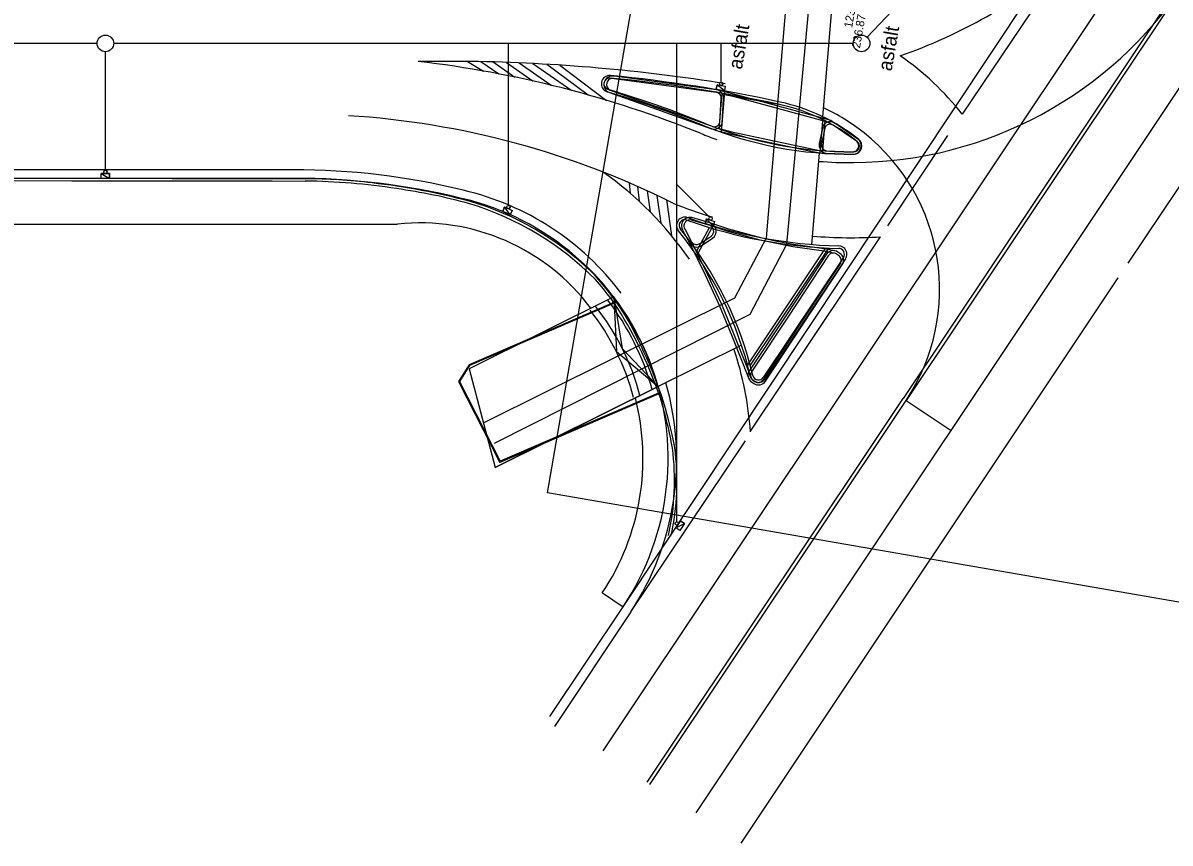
# Model space of a CAD drawing. Extents: x -264205 to -263659, y -1242401 to -1241986.
# Drawn here: x -263858.9 to -263790.1, y -1242352.1 to -1242302.9 of the extents above; entities that cross this region are included whole.
import ezdxf

# ---------------------------------------------------------------- set-up
doc = ezdxf.new("R2010")
doc.units = 0
for name, color, linetype in [('BOD_CISLO_2-4', 7, 'Continuous'), ('BOD_VYSKA_2-4', 7, 'Continuous'), ('POPIS_2-4', 7, 'Continuous'), ('PROJEKT_OBRUBNIKY_KOMUNIKACIE', 7, 'Continuous'), ('PROJEKT_TDZ_VODOROVNE', 7, 'Continuous'), ('RAM_NA_TLAC_2-4_1-250', 7, 'Continuous'), ('SITUACIA_DSP_2D', 7, 'Continuous'), ('SO_20-1_OBRUBNIKY_DOLNA_HRANA', 7, 'Continuous'), ('SO_20-1_OBRUBNIKY_HORNA_HRANA', 7, 'Continuous')]:
    doc.layers.add(name, color=color, linetype=linetype)

msp = doc.modelspace()

# ---------------------------------------------------------------- linework, layer by layer
at = {"layer": 'PROJEKT_OBRUBNIKY_KOMUNIKACIE'}
for p, q in [((-263816.964, -1242307.132), (-263817.145, -1242309.262)), ((-263816.802, -1242307.008), (-263817.012, -1242309.469)), ((-263816.819, -1242307.205), (-263813.706, -1242307.767)), ((-263810.912, -1242308.547), (-263811.097, -1242310.721)), ((-263810.781, -1242308.779), (-263810.935, -1242310.583)), ((-263842.601, -1242312.24), (-263924.192, -1242312.232)), ((-264038.443, -1242314.982), (-263836.403, -1242314.982)), ((-263818.469, -1242316.58), (-263817.711, -1242315.183)), ((-263818.453, -1242316.866), (-263817.491, -1242315.093)), ((-263810.751, -1242316.405), (-263815.43, -1242323.41)), ((-263810.576, -1242316.414), (-263815.268, -1242323.437)), ((-263809.676, -1242316.98), (-263814.48, -1242324.171)), ((-263809.551, -1242317.064), (-263814.356, -1242324.254)), ((-263823.444, -1242319.346), (-263832.112, -1242323.652)), ((-263813.542, -1242320.69), (-263813.542, -1242320.69)), ((-263832.112, -1242323.652), (-263830.544, -1242329.573)), ((-263820.775, -1242324.719), (-263830.544, -1242329.573)), ((-263824.127, -1242337.081), (-263822.88, -1242337.914)), ((-263827.28, -1242344.5), (-263822.88, -1242337.914))]:
    msp.add_line(p, q, dxfattribs=at)
for points in [[(-263832.112, -1242323.652), (-263830.544, -1242329.573), (-263820.775, -1242324.719), (-263821.24, -1242323.31), (-263821.84, -1242321.938), (-263822.869, -1242320.154), (-263823.444, -1242319.346), (-263832.112, -1242323.652)], [(-263823.444, -1242319.346), (-263823.288, -1242322.618), (-263820.775, -1242324.719)]]:
    msp.add_lwpolyline(points, dxfattribs=at)
for centre, radius, start, end in [((-263823.686, -1242306.574), 0.5, 84.50312, 253.37264), ((-263823.686, -1242306.574), 0.35, 84.50312, 253.37264), ((-263832, -1242392.966), 87.141, 77.74517, 84.50312), ((-263832, -1242392.966), 87.291, 77.74517, 84.50312), ((-263842.678, -1242370.168), 66.019, 68.01969, 73.37264), ((-263842.678, -1242370.168), 65.869, 68.01969, 73.37264), ((-263815.913, -1242318.902), 11.35, 51.49122, 77.74517), ((-263815.913, -1242318.902), 11.5, 51.49122, 77.74517), ((-263809.228, -1242287.295), 23.35, 248.01969, 270.4085), ((-263809.228, -1242287.295), 23.5, 248.01969, 270.4085), ((-263809.064, -1242310.295), 0.35, 270.4085, 51.49122), ((-263809.064, -1242310.295), 0.5, 270.4085, 51.49122), ((-263842.427, -1242353.351), 41.111, 76.13622, 90.24149), ((-263836.184, -1242329.025), 16, 326.2529, 76.96946), ((-263835.045, -1242327.715), 12.805, 36.92053, 96.08735), ((-263819.181, -1242315.066), 0.5, 70.28283, 219.38571), ((-263819.181, -1242315.066), 0.35, 70.28283, 219.38571), ((-263809.228, -1242287.295), 29.15, 250.28283, 268.56407), ((-263809.228, -1242287.295), 29, 250.28283, 268.56407), ((-263836.184, -1242329.025), 21.5, 13.26701, 39.38571), ((-263836.184, -1242329.025), 21.65, 13.26701, 39.38571), ((-263809.967, -1242316.786), 0.35, 326.2529, 88.56407), ((-263809.967, -1242316.786), 0.5, 326.2529, 88.56407), ((-263836.184, -1242329.025), 14.4, 14.72564, 38.11574), ((-263836.184, -1242329.025), 21.65, 13.26701, 14.95961), ((-263814.771, -1242323.977), 0.5, 193.26701, 326.2529), ((-263814.771, -1242323.977), 0.35, 193.26701, 326.2529), ((-263836.228, -1242329.021), 14.539, 326.33444, 14.41665)]:
    msp.add_arc(centre, radius, start, end, dxfattribs=at)
at = {"layer": 'PROJEKT_TDZ_VODOROVNE'}
for p, q in [((-263818.504, -1242350.278), (-263771.023, -1242279.037)), ((-263824.083, -1242346.553), (-263789.385, -1242294.564)), ((-263786.678, -1242296.363), (-263806.091, -1242325.442)), ((-263786.512, -1242296.474), (-263805.925, -1242325.553)), ((-263796.435, -1242299.302), (-263802.558, -1242308.383)), ((-263781.086, -1242300.054), (-263792.626, -1242317.328)), ((-263810.915, -1242308.545), (-263810.255, -1242300.841)), ((-263832.039, -1242305.232), (-263835.165, -1242305.232)), ((-263832.216, -1242305.232), (-263831.251, -1242305.806)), ((-263831.408, -1242305.243), (-263830.341, -1242305.974)), ((-263830.671, -1242305.261), (-263829.376, -1242306.167)), ((-263829.878, -1242305.286), (-263828.277, -1242306.405)), ((-263829.11, -1242305.316), (-263827.186, -1242306.661)), ((-263828.303, -1242305.354), (-263825.963, -1242306.972)), ((-263827.448, -1242305.4), (-263824.977, -1242307.241)), ((-263826.672, -1242305.448), (-263823.87, -1242307.573)), ((-263807.021, -1242315.081), (-263803.412, -1242309.66)), ((-263811.571, -1242316.2), (-263811.101, -1242310.72)), ((-263842.661, -1242311.732), (-263980.94, -1242311.732)), ((-263822.515, -1242312.506), (-263822.452, -1242313.137)), ((-263822.025, -1242312.72), (-263821.925, -1242313.608)), ((-263821.448, -1242312.98), (-263821.265, -1242314.247)), ((-263820.866, -1242313.273), (-263820.628, -1242314.918)), ((-263820.29, -1242313.528), (-263819.981, -1242315.667)), ((-263815.248, -1242327.389), (-263807.46, -1242315.74)), ((-263815.8, -1242352.081), (-263793.213, -1242318.207)), ((-263815.783, -1242322.239), (-263820.775, -1242324.719)), ((-263821.435, -1242348.441), (-263806.091, -1242325.442)), ((-263821.286, -1242348.578), (-263805.925, -1242325.553)), ((-263805.925, -1242325.553), (-263803.224, -1242327.353)), ((-263822.425, -1242338.218), (-263815.553, -1242327.973)), ((-263822.425, -1242338.218), (-263827.003, -1242345.095))]:
    msp.add_line(p, q, dxfattribs=at)
for points in [[(-263831.211, -1242326.873), (-263816.19, -1242319.41), (-263814.291, -1242315.804), (-263813.06, -1242301.353), (-263812.968, -1242299.181), (-263802.618, -1242291.831), (-263801.478, -1242290.893), (-263800.257, -1242289.755), (-263799.049, -1242288.464), (-263798.027, -1242287.218), (-263749.798, -1242216.488), (-263742.736, -1242211.145)], [(-263830.6, -1242328.105), (-263815.26, -1242320.378), (-263813.062, -1242316.188), (-263811.682, -1242301.389), (-263811.608, -1242300.055), (-263801.705, -1242293.023), (-263800.489, -1242292.021), (-263799.197, -1242290.817), (-263797.92, -1242289.454), (-263796.825, -1242288.118), (-263748.697, -1242217.536), (-263741.831, -1242212.341)]]:
    msp.add_lwpolyline(points, dxfattribs=at)
for centre, radius, start, end in [((-263816.477, -1242275.476), 31.135, 289.11393, 310.0684), ((-263809.228, -1242287.295), 24, 270.4085, 326.39685), ((-263815.913, -1242318.902), 17, 38.22666, 55.49063), ((-263842.678, -1242370.168), 65.369, 68.01969, 83.40081), ((-263833.602, -1242410.935), 105.714, 80.83552, 89.15278), ((-263815.913, -1242318.902), 12, 51.49122, 65.14678), ((-263842.518, -1242358.966), 50.583, 63.43291, 86.40224), ((-263809.228, -1242287.295), 24, 248.01969, 250.45738), ((-263815.913, -1242318.902), 12, 326.34085, 51.49122), ((-263842.485, -1242353.555), 41.823, 76.13622, 90.24149), ((-263809.228, -1242287.295), 24, 265.42107, 270.4085), ((-263836.184, -1242329.025), 21, 34.6339, 54.82374), ((-263836.225, -1242329.073), 16.555, 36.94624, 76.86936), ((-263809.228, -1242287.295), 28.5, 248.01969, 253.02566), ((-263809.228, -1242287.295), 28.5, 265.37106, 273.55623), ((-263836.184, -1242329.025), 21, 4.34908, 18.20748), ((-263836.225, -1242329.073), 16.555, 326.46684, 16.06545)]:
    msp.add_arc(centre, radius, start, end, dxfattribs=at)
at = {"layer": 'RAM_NA_TLAC_2-4_1-250'}
msp.add_lwpolyline([(-263827.42, -1242331.09), (-263769.814, -1241998.542), (-263696.654, -1242011.215), (-263754.26, -1242343.763)], close=True, dxfattribs=at)
at = {"layer": 'SITUACIA_DSP_2D'}
for p, q in [((-263822.88, -1242337.914), (-263734.49, -1242204.937)), ((-263780.353, -1242274.236), (-263808.248, -1242303.783)), ((-263854.415, -1242304.147), (-263903.413, -1242304.147)), ((-263809.091, -1242304.153), (-263853.415, -1242304.148)), ((-263829.755, -1242313.856), (-263829.755, -1242304.151)), ((-263819.667, -1242332.824), (-263819.667, -1242304.147)), ((-263817.005, -1242306.465), (-263817.005, -1242304.152)), ((-263853.915, -1242311.749), (-263853.915, -1242304.647)), ((-263817.296, -1242306.914), (-263817.252, -1242306.627)), ((-263817.252, -1242306.627), (-263817.296, -1242306.914)), ((-263816.802, -1242306.99), (-263817.296, -1242306.914)), ((-263817.296, -1242306.914), (-263816.802, -1242306.99)), ((-263817.252, -1242306.627), (-263816.757, -1242306.703)), ((-263816.802, -1242306.99), (-263817.252, -1242306.627)), ((-263816.802, -1242306.99), (-263817.252, -1242306.627)), ((-263816.757, -1242306.703), (-263816.802, -1242306.99)), ((-263816.964, -1242307.132), (-263817.145, -1242309.262)), ((-263816.803, -1242307.008), (-263817.012, -1242309.468)), ((-263810.912, -1242308.547), (-263811.097, -1242310.721)), ((-263810.781, -1242308.779), (-263810.935, -1242310.583)), ((-263980.94, -1242312.232), (-263857.327, -1242312.232)), ((-263842.601, -1242312.24), (-263924.192, -1242312.232)), ((-263854.165, -1242311.949), (-263853.665, -1242311.949)), ((-263854.165, -1242312.239), (-263854.165, -1242311.949)), ((-263854.165, -1242311.949), (-263853.665, -1242312.239)), ((-263854.165, -1242311.949), (-263853.665, -1242312.239)), ((-263853.665, -1242311.949), (-263854.165, -1242311.949)), ((-263853.665, -1242312.239), (-263854.165, -1242312.239)), ((-263853.665, -1242311.949), (-263853.665, -1242312.239)), ((-263853.665, -1242312.239), (-263853.665, -1242311.949)), ((-263817.708, -1242314.574), (-263819.667, -1242312.615)), ((-263830.101, -1242314.219), (-263829.983, -1242313.954)), ((-263829.983, -1242313.954), (-263830.101, -1242314.219)), ((-263829.645, -1242314.423), (-263830.101, -1242314.219)), ((-263830.101, -1242314.219), (-263829.645, -1242314.423)), ((-263829.983, -1242313.954), (-263829.527, -1242314.158)), ((-263829.645, -1242314.423), (-263829.983, -1242313.954)), ((-263829.645, -1242314.423), (-263829.983, -1242313.954)), ((-263829.527, -1242314.158), (-263829.645, -1242314.423)), ((-264038.443, -1242314.982), (-263836.403, -1242314.982)), ((-263818.469, -1242316.58), (-263817.711, -1242315.183)), ((-263818.453, -1242316.866), (-263817.491, -1242315.093)), ((-263817.966, -1242314.94), (-263817.874, -1242314.665)), ((-263817.874, -1242314.665), (-263817.966, -1242314.94)), ((-263817.492, -1242315.099), (-263817.966, -1242314.94)), ((-263817.966, -1242314.94), (-263817.492, -1242315.099)), ((-263817.874, -1242314.665), (-263817.4, -1242314.824)), ((-263817.492, -1242315.099), (-263817.874, -1242314.665)), ((-263817.492, -1242315.099), (-263817.874, -1242314.665)), ((-263817.4, -1242314.824), (-263817.492, -1242315.099)), ((-263810.751, -1242316.405), (-263815.43, -1242323.41)), ((-263810.576, -1242316.414), (-263815.268, -1242323.437)), ((-263809.676, -1242316.98), (-263814.48, -1242324.171)), ((-263809.551, -1242317.064), (-263814.356, -1242324.254)), ((-263823.444, -1242319.346), (-263832.112, -1242323.652)), ((-263823.444, -1242319.346), (-263832.112, -1242323.652)), ((-263823.444, -1242319.346), (-263822.93, -1242322.44)), ((-263822.869, -1242320.154), (-263823.444, -1242319.346)), ((-263821.84, -1242321.938), (-263822.869, -1242320.154)), ((-263813.542, -1242320.69), (-263813.542, -1242320.69)), ((-263813.542, -1242320.69), (-263813.542, -1242320.69)), ((-263821.24, -1242323.31), (-263821.84, -1242321.938)), ((-263822.93, -1242322.44), (-263820.775, -1242324.719)), ((-263820.775, -1242324.719), (-263821.24, -1242323.31)), ((-263832.112, -1242323.652), (-263830.544, -1242329.573)), ((-263832.112, -1242323.652), (-263830.544, -1242329.573)), ((-263820.775, -1242324.719), (-263830.544, -1242329.573)), ((-263830.544, -1242329.573), (-263820.775, -1242324.719)), ((-263819.723, -1242333.187), (-263819.444, -1242332.772)), ((-263819.723, -1242333.187), (-263819.203, -1242332.933)), ((-263819.203, -1242332.933), (-263819.482, -1242333.349)), ((-263819.444, -1242332.772), (-263819.203, -1242332.933)), ((-263819.482, -1242333.349), (-263819.723, -1242333.187)), ((-263824.127, -1242337.081), (-263822.88, -1242337.914)), ((-263827.28, -1242344.5), (-263822.88, -1242337.914))]:
    msp.add_line(p, q, dxfattribs=at)
msp.add_lwpolyline([(-263819.723, -1242333.187), (-263819.203, -1242332.933), (-263819.444, -1242332.772)], close=True, dxfattribs=at)
for centre, radius in [((-263853.915, -1242304.147), 0.5), ((-263808.591, -1242304.147), 0.5), ((-263817.005, -1242306.565), 0.1), ((-263853.915, -1242311.849), 0.1), ((-263829.755, -1242313.956), 0.1), ((-263817.637, -1242314.644), 0.1), ((-263819.667, -1242332.924), 0.1)]:
    msp.add_circle(centre, radius, dxfattribs=at)
for centre, radius, start, end in [((-263823.686, -1242306.574), 0.5, 84.50312, 253.37264), ((-263823.686, -1242306.574), 0.35, 84.50312, 253.37264), ((-263832, -1242392.966), 87.141, 77.74517, 84.50312), ((-263832, -1242392.966), 87.291, 77.74517, 84.50312), ((-263842.678, -1242370.168), 66.019, 68.01969, 73.37264), ((-263842.678, -1242370.168), 65.869, 68.01969, 73.37264), ((-263815.913, -1242318.902), 11.35, 51.49122, 77.74517), ((-263815.913, -1242318.902), 11.5, 51.49122, 77.74517), ((-263809.228, -1242287.295), 23.35, 248.01969, 270.4085), ((-263809.228, -1242287.295), 23.5, 248.01969, 270.4085), ((-263809.064, -1242310.295), 0.35, 270.4085, 51.49122), ((-263809.064, -1242310.295), 0.5, 270.4085, 51.49122), ((-263842.427, -1242353.351), 41.111, 76.13622, 90.24149), ((-263836.184, -1242329.025), 16, 326.2529, 76.96946), ((-263835.045, -1242327.715), 12.805, 36.92053, 96.08735), ((-263819.181, -1242315.066), 0.5, 70.28283, 219.38571), ((-263819.181, -1242315.066), 0.35, 70.28283, 219.38571), ((-263809.228, -1242287.295), 29.15, 250.28283, 268.56407), ((-263809.228, -1242287.295), 29, 250.28283, 268.56407), ((-263836.184, -1242329.025), 21.5, 13.26701, 39.38571), ((-263836.184, -1242329.025), 21.65, 13.26701, 39.38571), ((-263809.967, -1242316.786), 0.35, 326.2529, 88.56407), ((-263809.967, -1242316.786), 0.5, 326.2529, 88.56407), ((-263836.184, -1242329.025), 14.8, 14.72564, 38.11574), ((-263836.184, -1242329.025), 15.6, 15.3332, 37.50818), ((-263836.184, -1242329.025), 21.65, 13.26701, 14.95961), ((-263814.771, -1242323.977), 0.5, 193.26701, 326.2529), ((-263814.771, -1242323.977), 0.35, 193.26701, 326.2529), ((-263836.228, -1242329.021), 14.539, 326.33444, 14.41665)]:
    msp.add_arc(centre, radius, start, end, dxfattribs=at)
at = {"layer": 'SO_20-1_OBRUBNIKY_DOLNA_HRANA'}
for p, q in [((-263817.063, -1242306.967), (-263817.288, -1242306.937)), ((-263810.406, -1242308.774), (-263817.063, -1242306.967)), ((-263820.884, -1242308.09), (-263817.579, -1242309.261)), ((-263810.406, -1242308.774), (-263810.197, -1242308.936)), ((-263817.365, -1242309.349), (-263817.579, -1242309.261)), ((-263810.829, -1242310.758), (-263810.713, -1242310.731)), ((-263815.174, -1242324.45), (-263815.054, -1242324.532))]:
    msp.add_line(p, q, dxfattribs=at)
for points in [[(-263817.288, -1242306.937), (-263820.425, -1242306.521), (-263823.4, -1242306.12)], [(-263823.703, -1242307.096), (-263820.884, -1242308.09)], [(-263816.946, -1242308.93), (-263816.856, -1242307.496)], [(-263808.866, -1242309.846), (-263810.197, -1242308.936)], [(-263817.365, -1242309.349), (-263816.395, -1242309.589), (-263811.523, -1242310.634), (-263810.829, -1242310.758)], [(-263810.897, -1242309.063), (-263811.127, -1242310.142)], [(-263810.713, -1242310.731), (-263809.129, -1242310.789)], [(-263927.909, -1242312.235), (-263920.91, -1242312.234), (-263913.915, -1242312.225), (-263906.912, -1242312.227), (-263898.896, -1242312.208), (-263891.9, -1242312.209), (-263883.905, -1242312.21), (-263878.731, -1242312.212), (-263870.923, -1242312.226), (-263863.907, -1242312.232), (-263855.93, -1242312.232)], [(-263855.93, -1242312.232), (-263849.929, -1242312.239), (-263843.916, -1242312.251), (-263841.932, -1242312.261)], [(-263817.69, -1242314.913), (-263818.761, -1242314.594)], [(-263810.206, -1242316.578), (-263810.698, -1242316.485), (-263812.677, -1242316.21), (-263813.66, -1242316.015), (-263814.633, -1242315.798), (-263816.547, -1242315.28), (-263817.69, -1242314.913)], [(-263819.319, -1242315.341), (-263818.902, -1242316.108)], [(-263818.201, -1242316.278), (-263817.525, -1242315.828)], [(-263818.902, -1242316.108), (-263817.973, -1242318.024), (-263817.129, -1242319.833), (-263816.363, -1242321.682), (-263815.372, -1242324.19)], [(-263810.704, -1242316.807), (-263813.097, -1242320.419), (-263815.312, -1242323.75)], [(-263809.892, -1242316.735), (-263810.008, -1242316.657)], [(-263814.347, -1242324.391), (-263812.142, -1242321.053), (-263809.743, -1242317.428)]]:
    msp.add_lwpolyline(points, dxfattribs=at)
for centre, major_axis, ratio, start_param, end_param in [((-263823.524, -1242306.605), (0.185, 0.465), 0.999783, 0.129335, 1.693518), ((-263823.537, -1242306.629), (-0.201, -0.453), 0.999743, 4.819194, 6.358079), ((-263817.347, -1242307.429), (-0.223, 0.443), 0.999317, 4.112578, 5.697553), ((-263817.423, -1242308.788), (0.483, 0.121), 0.999839, 4.148248, 5.748493), ((-263810.483, -1242309.349), (-0.502, 0.041), 0.998209, 4.188918, 5.758624), ((-263810.643, -1242310.242), (0.359, -0.34), 0.999903, 3.695611, 5.327884), ((-263809.118, -1242310.288), (0.193, 0.471), 0.999988, 4.374498, 6.15423), ((-263809.106, -1242310.293), (-0.189, -0.46), 0.999728, 0.34373, 1.224576), ((-263842.029, -1242344.44), (-32.124, -3.857), 0.994471, 4.466507, 4.590549), ((-263842.443, -1242352.313), (-40.262, 2.734), 0.992518, 4.518911, 4.667632), ((-263836.917, -1242330.389), (-12.568, 12.147), 0.998664, 4.713467, 5.197044), ((-263818.893, -1242315.066), (0.148, -0.467), 0.999867, 2.562738, 4.12235), ((-263818.868, -1242315.085), (0.045, -0.517), 0.999806, 4.320521, 5.104257), ((-263817.803, -1242315.406), (0.39, 0.323), 0.999315, 4.602925, 6.93754), ((-263818.47, -1242315.857), (-0.486, 0.118), 0.999915, 0.764319, 2.377274), ((-263810.284, -1242317.065), (-0.259, 0.419), 0.999812, 5.134851, 6.750861), ((-263810.141, -1242317.151), (0.065, 0.481), 0.999991, 4.238012, 5.877529), ((-263835.299, -1242328.082), (-9.097, 11.695), 0.990566, 4.45941, 4.823964), ((-263842.758, -1242332.613), (-5.115, 22.811), 0.999168, 4.674361, 4.949582), ((-263814.893, -1242324.031), (-0.282, 0.418), 0.999941, 0.386314, 1.958336), ((-263814.769, -1242324.118), (0.274, -0.422), 0.999972, 5.104611, 6.703858), ((-263834.807, -1242330.397), (-3.889, 14.649), 0.999894, 4.234216, 4.586906)]:
    msp.add_ellipse(centre, major_axis=major_axis, ratio=ratio, start_param=start_param, end_param=end_param, dxfattribs=at)
at = {"layer": 'SO_20-1_OBRUBNIKY_HORNA_HRANA'}
for p, q in [((-263817.531, -1242309.127), (-263820.836, -1242307.954)), ((-263823.41, -1242319.718), (-263823.601, -1242319.436)), ((-263823.438, -1242319.676), (-263823.41, -1242319.718)), ((-263832.744, -1242324.409), (-263830.277, -1242329.263)), ((-263832.687, -1242324.411), (-263830.254, -1242329.198)), ((-263815.091, -1242324.327), (-263814.973, -1242324.409)), ((-263820.742, -1242325.152), (-263830.277, -1242329.263)), ((-263820.759, -1242325.105), (-263830.254, -1242329.198)), ((-263820.759, -1242325.105), (-263820.619, -1242325.485)), ((-263820.742, -1242325.152), (-263820.759, -1242325.105))]:
    msp.add_line(p, q, dxfattribs=at)
for points in [[(-263817.303, -1242307.084), (-263820.446, -1242306.665), (-263823.42, -1242306.265)], [(-263823.65, -1242306.961), (-263820.836, -1242307.954)], [(-263817.088, -1242308.892), (-263817, -1242307.47)], [(-263810.62, -1242308.866), (-263814.206, -1242307.895), (-263816.937, -1242307.151)], [(-263817.212, -1242309.239), (-263816.368, -1242309.447), (-263811.493, -1242310.492), (-263811.003, -1242310.58)], [(-263810.775, -1242309.146), (-263810.987, -1242310.177)], [(-263808.95, -1242309.964), (-263810.282, -1242309.057)], [(-263810.691, -1242310.583), (-263809.125, -1242310.643)], [(-263927.907, -1242312.381), (-263920.909, -1242312.378), (-263913.91, -1242312.365), (-263906.907, -1242312.358), (-263898.91, -1242312.357), (-263891.902, -1242312.354), (-263883.907, -1242312.356), (-263878.731, -1242312.358), (-263870.924, -1242312.368), (-263863.913, -1242312.368), (-263855.926, -1242312.378)], [(-263855.926, -1242312.378), (-263849.928, -1242312.38), (-263843.916, -1242312.392), (-263841.931, -1242312.403)], [(-263817.727, -1242315.051), (-263818.789, -1242314.736)], [(-263810.25, -1242316.722), (-263810.709, -1242316.628), (-263812.704, -1242316.349), (-263813.689, -1242316.152), (-263814.669, -1242315.935), (-263816.585, -1242315.418), (-263817.727, -1242315.051)], [(-263819.192, -1242315.267), (-263818.773, -1242316.035)], [(-263818.28, -1242316.154), (-263817.608, -1242315.704)], [(-263818.773, -1242316.035), (-263817.84, -1242317.955), (-263816.991, -1242319.776), (-263816.227, -1242321.632), (-263815.233, -1242324.135)], [(-263810.584, -1242316.886), (-263812.978, -1242320.501), (-263815.192, -1242323.831)], [(-263809.97, -1242316.859), (-263810.089, -1242316.78)], [(-263814.473, -1242324.31), (-263812.268, -1242320.976), (-263809.861, -1242317.343)], [(-263823.438, -1242319.676), (-263832.117, -1242323.409), (-263832.744, -1242324.409)], [(-263823.41, -1242319.718), (-263832.083, -1242323.449), (-263832.687, -1242324.411)]]:
    msp.add_lwpolyline(points, dxfattribs=at)
for centre, major_axis, ratio, start_param, end_param in [((-263823.519, -1242306.604), (0.235, 0.264), 0.999068, 0.442251, 2.051271), ((-263823.525, -1242306.629), (-0.123, -0.333), 0.999597, 4.748011, 6.276343), ((-263817.341, -1242307.426), (-0.027, 0.343), 0.999831, 4.506293, 6.094133), ((-263817.42, -1242308.802), (-0.293, -0.18), 0.999477, 0.692286, 2.325931), ((-263810.484, -1242309.349), (-0.307, 0.179), 0.999697, 4.635173, 6.202132), ((-263810.652, -1242310.243), (0.136, -0.314), 0.999837, 4.109578, 5.759605), ((-263809.124, -1242310.284), (-0.341, 0.127), 0.999992, 2.744279, 4.570945), ((-263809.115, -1242310.288), (-0.172, -0.311), 0.99925, 0.476223, 1.31312), ((-263842.277, -1242350.519), (-36.177, 12.321), 0.997094, 4.886995, 5.030708), ((-263841.309, -1242347.152), (-34.744, 1.786), 0.995607, 4.494833, 4.62376), ((-263837.329, -1242331.009), (-13.346, 12.171), 0.997839, 4.663107, 5.155176), ((-263818.883, -1242315.084), (-0.063, -0.354), 0.999357, 4.579753, 5.422246), ((-263818.881, -1242315.086), (0.067, -0.355), 0.999729, 2.699114, 4.216297), ((-263817.816, -1242315.405), (0.31, 0.192), 0.999422, 4.763927, 7.052938), ((-263818.467, -1242315.846), (0.335, -0.13), 0.999891, 4.064262, 5.628365), ((-263810.285, -1242317.071), (-0.288, 0.202), 0.999767, 4.729783, 6.338871), ((-263810.156, -1242317.155), (-0.077, 0.341), 0.999809, 3.924248, 5.50053), ((-263849.035, -1242339.606), (-22.317, 24.858), 0.971582, 4.653005, 4.696983), ((-263843.342, -1242332.884), (-0.791, 23.885), 0.999409, 5.010846, 5.262764), ((-263814.885, -1242324.027), (-0.325, 0.164), 0.999886, 6.182815, 7.71937), ((-263814.772, -1242324.114), (0.357, 0.013), 0.998096, 4.078566, 5.665653), ((-263846.347, -1242333.123), (-8.061, 25.7), 0.996418, 4.585653, 4.697064), ((-263834.962, -1242330.362), (1.128, 15.134), 0.999102, 4.568049, 4.916141)]:
    msp.add_ellipse(centre, major_axis=major_axis, ratio=ratio, start_param=start_param, end_param=end_param, dxfattribs=at)

# ---------------------------------------------------------------- texts
at = {"layer": 'BOD_CISLO_2-4'}
msp.add_text('1237', height=0.5, rotation=80.1724, dxfattribs=at).set_placement((-263809.156, -1242303.248))
at = {"layer": 'BOD_VYSKA_2-4'}
msp.add_text('236.87', height=0.5, rotation=80.1724, dxfattribs=at).set_placement((-263808.685, -1242304.463))
at = {"layer": 'POPIS_2-4'}
for p in [(-263815.766, -1242305.745), (-263806.789, -1242305.849)]:
    msp.add_text('asfalt', height=0.8437, rotation=80.17241, dxfattribs=at).set_placement(p)

doc.saveas('drawing.dxf')
